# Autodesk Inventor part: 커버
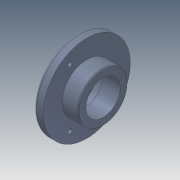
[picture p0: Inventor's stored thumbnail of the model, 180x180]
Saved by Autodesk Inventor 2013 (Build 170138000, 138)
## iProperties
Company: 한국ATC센터
Created: 2014-10
Part Number: 커버
Document SubType Name: Modeling
Designer: 한국ATC센터
Density: 2.71 g/cm^3
Material: 알루미늄-6061
Mass: 189.969 g
Surface Area: 197.235 cm^2
Volume: 70.0991 cm^3
Author: KYOUNG IL JANG
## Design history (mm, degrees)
sketch "스케치1"
  geometry: L1 (-13.5, 0)-(13.5, 0); L2 (-13.5, 0)-(-13.5, 45.5); L3 (-13.5, 45.5)-(-3.5, 45.5); L4 (-3.5, 45.5)-(-3.5, 26); L5 (-3.5, 26)-(13.5, 26); L6 (13.5, 26)-(13.5, 0); 2 further points
  constraints: 12 end point, 3 parallel, 2 perpendicular, 1 coincident, 1 horizontal, 1 midpoint
  dimensions: "d0" = 27 distance of L1.start L1.end; "d1" = 91 diameter of L3 L1; "d2" = 52 diameter of L5 L1; "d3" = 10 distance of L2.end L3.end
revolve "회전1" sketch "스케치1" stored, may be unused: angle "d4" = 90 deg
hole "구멍1" diameter "d7" = 36; stored, may be unused: countersink angle "d11" = 90 deg, drill point angle "d13" = 118 deg; dims "d5" = 10, "d6" = 10, "d8" = 6, "d9" = 40, "d10" = 8.3, "d12" = 8
sketch "스케치2"
  geometry: 2 further points
  constraints: 1 vertical alignment
  dimensions: "d14" = 35 distance of point (0, 0) point (0, 35)
hole "구멍2" sketch "스케치2" at (0, 35) diameter "d15" = 4.5; stored, may be unused: countersink angle "d19" = 90 deg, drill point angle "d21" = 118 deg; dims "d16" = 6, "d17" = 8, "d18" = 4.4, "d20" = 8
chamfer "모따기1" distance "d25" = 0.8; stored, may be unused: second distance "d26" = 2, angle "d27" = 30 deg
fillet "모깎기1" dims "d28" = 0.1, "d29" = 3
chamfer "모따기2" distance "d30" = 1; stored, may be unused: second distance "d31" = 2, angle "d32" = 30 deg
node "솔리드1"
pattern_circular "원형 패턴1" dims angle "d23" = 360 deg
